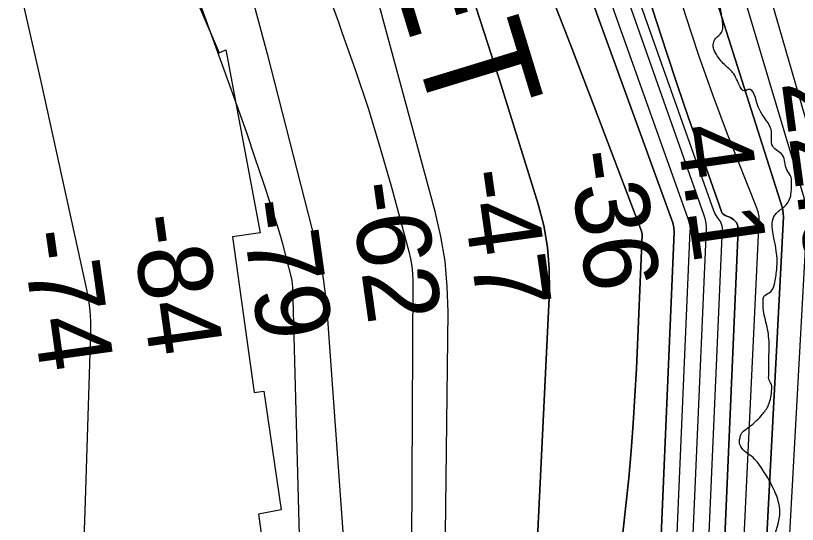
# Model space of a CAD drawing. Extents: x 3329297 to 3367176, y 649250 to 674653.
# Drawn here: x 3342123 to 3342831, y 664290 to 664750 of the extents above; entities that cross this region are included whole.
import ezdxf

# ---------------------------------------------------------------- set-up
doc = ezdxf.new("R2010")
doc.units = 0
for name, color, linetype in [('V-RIVR-EDGE', 7, 'Continuous'), ('V-RIVR-RANG', 7, 'Continuous'), ('V-RRAP-RVMT', 7, 'Continuous'), ('V-RRAP-RVMT-IDEN', 7, 'Continuous'), ('V-TOPO-DPTH', 7, 'Continuous'), ('V-TOPO-MAJR', 7, 'Continuous'), ('V-TOPO-MINR', 7, 'Continuous'), ('V-TOPO-WATR', 7, 'Continuous')]:
    doc.layers.add(name, color=color, linetype=linetype)

msp = doc.modelspace()

# ---------------------------------------------------------------- linework, layer by layer
at = {"layer": 'V-RIVR-EDGE'}
msp.add_spline([(3342816.41, 664076.7), (3342812.76, 664100.73), (3342811.24, 664114.69), (3342810.49, 664125.17), (3342811.67, 664129.43), (3342815.94, 664131.36), (3342822.14, 664130.96), (3342827.58, 664133.66), (3342827.98, 664138.7), (3342825.71, 664163.52), (3342823.01, 664169.35), (3342818.01, 664185.26), (3342816.5, 664200), (3342816.91, 664208.92), (3342818.1, 664220.94), (3342817.34, 664227.14), (3342814.66, 664243.44), (3342809.27, 664257.41), (3342808.51, 664264.01), (3342808.92, 664272.54), (3342814.79, 664296.18), (3342814.82, 664305.49), (3342810.59, 664319.46), (3342799.78, 664338.87), (3342790.88, 664350.14), (3342779.66, 664360.25), (3342778.51, 664365.3), (3342779.3, 664369.17), (3342779.69, 664370.72), (3342785.91, 664376.91), (3342798.35, 664388.13), (3342804.18, 664396.26), (3342807.71, 664410.21), (3342807.34, 664416.8), (3342805.02, 664421.46), (3342805.03, 664424.18), (3342805.05, 664435.04), (3342805.48, 664451.32), (3342803.59, 664468.39), (3342800.14, 664485.46), (3342800.15, 664492.05), (3342800.55, 664495.93), (3342805.6, 664499.41), (3342810.27, 664507.15), (3342811.45, 664513.74), (3342812.65, 664526.54), (3342808.84, 664554.08), (3342808.48, 664564.55), (3342811.98, 664571.52), (3342819.76, 664577.71), (3342825.21, 664588.56), (3342825.62, 664596.7), (3342825.25, 664604.07), (3342821.39, 664610.67), (3342817.54, 664623.86), (3342808.64, 664632.03), (3342807.5, 664639.01), (3342807.51, 664645.61), (3342805.59, 664651.04), (3342795.55, 664667.74), (3342786.28, 664683.28), (3342782.79, 664682.12), (3342779.3, 664685.62), (3342772.36, 664698.82), (3342765.01, 664705.82), (3342757.66, 664715.15), (3342754.96, 664720.97), (3342754.97, 664725.24), (3342756.92, 664729.5), (3342762.36, 664734.91), (3342763.16, 664745.77), (3342759.34, 664768.66), (3342756.66, 664780.69), (3342750.49, 664796.21), (3342738.91, 664818.35), (3342728.88, 664839.31), (3342718.83, 664850.59), (3342704.53, 664870.4), (3342673.21, 664906.93), (3342667.03, 664917.03), (3342662.4, 664928.67), (3342645.77, 664948.1), (3342638.82, 664957.43), (3342632.64, 664969.85), (3342630.72, 664978), (3342626.86, 664984.99), (3342614.87, 664996.66), (3342611.39, 664999.38), (3342609.84, 665001.32), (3342609.85, 665006.36), (3342606.76, 665010.25), (3342597.86, 665020.35), (3342593.22, 665025.41), (3342592.47, 665033.17), (3342590.94, 665044.42), (3342589.42, 665054.5), (3342588.28, 665065.36), (3342585.98, 665077), (3342585.23, 665086.7), (3342585.25, 665096.4), (3342584.88, 665101.05), (3342582.95, 665104.16), (3342580.25, 665109.59), (3342577.16, 665116.97), (3342577.18, 665122.79), (3342577.2, 665131.71), (3342577.22, 665142.56), (3342577.25, 665154.2), (3342576.12, 665167.77), (3342572.7, 665192.99), (3342566.93, 665215.11), (3342563.48, 665229.47), (3342558.85, 665239.95), (3342557.31, 665244.22), (3342555.4, 665255.47), (3342553.11, 665268.66), (3342549.27, 665284.57), (3342541.57, 665307.08), (3342537.34, 665321.83), (3342531.95, 665340.07), (3342533.51, 665343.55), (3342533.53, 665349.76), (3342526.98, 665368.39), (3342525.46, 665379.64), (3342523.54, 665388.18), (3342518.15, 665403.7), (3342515.47, 665416.12), (3342514.34, 665430.86), (3342508.57, 665450.65), (3342503.19, 665470.83), (3342492.38, 665490.63), (3342491.63, 665499.17), (3342490.87, 665508.48), (3342486.28, 665532.92), (3342483.6, 665545.33), (3342477.81, 665557.76), (3342475.93, 665580.26), (3342474.8, 665594.22), (3342470.17, 665605.48), (3342467.87, 665614.4), (3342467.13, 665629.53), (3342466.39, 665643.49), (3342466.82, 665662.1), (3342467.25, 665679.55), (3342463.41, 665695.46), (3342454.93, 665713.71), (3342445.67, 665732.35), (3342448.39, 665735.45), (3342449.55, 665735.05), (3342454.58, 665728.84), (3342456.13, 665730.38), (3342456.13, 665730.77), (3342455.37, 665734.65), (3342442.22, 665750.97), (3342428.7, 665771.56), (3342413.65, 665800.68), (3342398.6, 665832.52), (3342380.47, 665869.41), (3342358.86, 665914.06), (3342350, 665938.51), (3342337.27, 665963.36), (3342312.2, 666021.59), (3342297.17, 666058.47), (3342281.74, 666092.64), (3342274.81, 666112.43), (3342267.5, 666136.11), (3342262.92, 666165.98), (3342261.43, 666190.8), (3342261.45, 666198.56), (3342257.57, 666197.79), (3342255.25, 666199.74), (3342252.93, 666205.17), (3342252.57, 666212.54), (3342252.58, 666219.13), (3342250.29, 666232.71), (3342241.82, 666258.33), (3342236.07, 666285.87), (3342231.81, 666288.99), (3342227.55, 666291.71), (3342219.05, 666302.59), (3342218.67, 666306.86), (3342219.07, 666312.29), (3342210.16, 666314.25), (3342205.13, 666318.91), (3342203.98, 666324.35), (3342203.99, 666330.16), (3342202.08, 666339.09), (3342191.65, 666356.56), (3342180.04, 666369), (3342175.41, 666377.55), (3342164.99, 666396.96), (3342154.58, 666421.81), (3342139.95, 666463.34), (3342130.7, 666487.79), (3342122.99, 666506.43), (3342111.8, 666527.4), (3342098.68, 666554.19), (3342094.83, 666565.83), (3342092.54, 666581.74), (3342088.69, 666594.54), (3342085.25, 666612.78), (3342082.17, 666622.09), (3342072.89, 666631.81), (3342063.22, 666645.41), (3342057.44, 666657.83), (3342049.73, 666678.02), (3342048.22, 666693.14), (3342050.17, 666696.63), (3342050.96, 666704.38), (3342046.71, 666709.05), (3342039.36, 666716.82), (3342032.41, 666729.25), (3342015.81, 666761.09), (3342003.06, 666780.9), (3341996.09, 666786.35), (3341994.95, 666792.55), (3341992.63, 666796.44), (3341982.97, 666811.97), (3341967.13, 666835.28), (3341953.59, 666848.89), (3341946.63, 666857.44), (3341940.45, 666867.92), (3341935.81, 666874.14), (3341919.16, 666884.26), (3341915.69, 666890.09), (3341911.45, 666900.18), (3341899.85, 666913.78), (3341894.82, 666921.16), (3341889.03, 666931.65), (3341869.32, 666956.91), (3341855.01, 666974.78), (3341848.82, 666978.67), (3341839.53, 666986.84), (3341829.09, 667000.44), (3341821.76, 667015.19), (3341819.07, 667024.89), (3341817.15, 667031.1), (3341806.31, 667038.89), (3341788.13, 667056.77), (3341778.46, 667069.98), (3341769.56, 667076.21), (3341762.98, 667079.71), (3341756.02, 667089.04), (3341748.29, 667099.53), (3341738.62, 667112.35), (3341730.89, 667120.12), (3341719.29, 667133.73), (3341714.66, 667143.05), (3341706.55, 667156.64), (3341694.95, 667171.79), (3341682.22, 667198.97), (3341673.73, 667217.22), (3341665.66, 667244.77), (3341658.35, 667270.77), (3341654.5, 667280.86), (3341646.79, 667297.56), (3341633.67, 667325.51), (3341621.31, 667347.26), (3341603.92, 667370.57), (3341601.61, 667379.11), (3341595.05, 667392.31), (3341586.57, 667412.5), (3341578.1, 667435.79), (3341568.43, 667448.22), (3341554.13, 667467.65), (3341537.52, 667492.51), (3341516.66, 667523.97), (3341476.08, 667581.85), (3341429.71, 667650.22), (3341398.03, 667697.22), (3341370.98, 667737.23), (3341354.76, 667763.64), (3341343.55, 667778.41), (3341338.9, 667782.3), (3341332.33, 667790.07), (3341325.39, 667805.99), (3341317.65, 667814.15), (3341305.28, 667827.37), (3341300.64, 667833.19), (3341282.89, 667869.69), (3341259.72, 667911.24), (3341224.58, 667969.5), (3341190.57, 668018.45), (3341159.67, 668067), (3341126.02, 668105.48), (3341085.81, 668151.72), (3341034.77, 668213.12), (3340998.8, 668250.83), (3340967.07, 668282.32), (3340929.92, 668312.66), (3340887.35, 668349.99), (3340852.52, 668378), (3340818.08, 668406.01), (3340783.64, 668439.06), (3340747.67, 668475.99), (3340722.92, 668504.36), (3340704.36, 668525.73), (3340693.92, 668537.01), (3340680.75, 668543.24), (3340672.61, 668546.75), (3340664.48, 668552.59), (3340650.93, 668563.48), (3340645.91, 668568.92), (3340640.88, 668576.69), (3340634.7, 668584.08), (3340619.62, 668601.57), (3340609.54, 668604.69), (3340603.74, 668608.97), (3340599.1, 668614.41), (3340595.62, 668621.01), (3340589.43, 668627.24), (3340567.76, 668645.9), (3340549.95, 668659.13), (3340496.93, 668702.7), (3340430.76, 668760.64), (3340383.93, 668798.76), (3340346.77, 668824.45), (3340316.96, 668845.08), (3340289.86, 668863.37), (3340255.41, 668891.77), (3340209.37, 668936.09), (3340181.13, 668962.92), (3340159.06, 668977.32), (3340134.29, 668996.39), (3340120.75, 669009.22), (3340113.4, 669017.77), (3340109.92, 669023.59), (3340107.6, 669025.92), (3340099.85, 669026.72), (3340094.42, 669027.9), (3340089.39, 669030.24), (3340085.14, 669036.45), (3340084.76, 669043.04), (3340082.06, 669046.15), (3340066.19, 669058.99), (3340051.1, 669071.44), (3340041.8, 669077.66), (3339987.61, 669116.19), (3339929.52, 669149.3), (3339882.28, 669177.34), (3339823.8, 669212), (3339768.82, 669245.87), (3339704.94, 669289.46), (3339659.64, 669320.6), (3339613.98, 669359.49), (3339576.03, 669382.85), (3339562.87, 669392.97), (3339559.39, 669394.53), (3339555.89, 669394.15), (3339553.17, 669389.89), (3339550.84, 669388.73), (3339546.19, 669392.24), (3339540.39, 669395.35), (3339537.28, 669393.03), (3339533.01, 669392.66), (3339518.67, 669398.12), (3339507.83, 669404.74), (3339498.93, 669411.35), (3339490.01, 669411.38), (3339486.53, 669416.04), (3339483.43, 669417.6), (3339473.36, 669420.73), (3339460.58, 669427.74), (3339447.8, 669435.52), (3339435.41, 669443.31), (3339423.8, 669453.42), (3339413.36, 669464.7), (3339407.94, 669471.3), (3339393.62, 669479.48), (3339378.13, 669489.21), (3339357.61, 669502.45), (3339355.67, 669504.78), (3339358.39, 669506.33), (3339359.56, 669509.43), (3339359.18, 669510.98), (3339356.48, 669515.25), (3339347.17, 669516.82), (3339341.34, 669512.57), (3339338.24, 669513.36), (3339320.82, 669525.81), (3339311.15, 669534.75), (3339296.06, 669548.75), (3339293.35, 669550.31), (3339286.37, 669549.16), (3339280.93, 669546.46), (3339277.05, 669546.47), (3339268.14, 669549.98), (3339250.71, 669559.72), (3339229.04, 669575.67), (3339210.84, 669586.97), (3339202.33, 669595.13), (3339200.4, 669599.4), (3339200.02, 669604.83), (3339198.1, 669611.04), (3339183.01, 669622.71), (3339166.35, 669632.45)], degree=3, dxfattribs=at)
at = {"layer": 'V-RRAP-RVMT'}
for p, q in [((3342290.19, 664757.35), (3342307.62, 664716.49)), ((3342307.62, 664716.49), (3342313.85, 664719.1)), ((3342313.85, 664719.1), (3342344.64, 664553.67)), ((3342344.64, 664553.67), (3342319.79, 664549.9)), ((3342319.79, 664549.9), (3342339.2, 664409.04)), ((3342339.2, 664409.04), (3342348.14, 664410.37)), ((3342348.14, 664410.37), (3342363.8, 664302.78)), ((3342363.8, 664302.78), (3342343.39, 664298.89)), ((3342343.39, 664298.89), (3342361.53, 664168.96))]:
    msp.add_line(p, q, dxfattribs=at)
at = {"layer": 'V-TOPO-DPTH'}
for points in [[(3342213.91, 666344.24), (3342248.03, 666262.65), (3342280.72, 666180.47), (3342312.47, 666097.91), (3342483.02, 665642.52), (3342485.21, 665636.51), (3342487.34, 665630.48), (3342489.35, 665624.41), (3342491.3, 665618.32), (3342634.58, 665157.16), (3342664.89, 665059.88), (3342695.3, 664962.62), (3342725.85, 664865.41), (3342756.5, 664768.24), (3342817.37, 664575.8), (3342817.87, 664573.91), (3342818.26, 664571.02), (3342818.28, 664568.1), (3342772.99, 663696.25)], [(3342162.24, 666335.77), (3342410.61, 665656.31), (3342418.95, 665633.05), (3342427.09, 665609.73), (3342434.94, 665586.3), (3342442.6, 665562.81), (3342703.31, 664745.72), (3342712.82, 664716.35), (3342722.51, 664687.04), (3342732.45, 664657.82), (3342742.57, 664628.66), (3342762.18, 664572.94), (3342762.76, 664571.81), (3342763.49, 664570.82), (3342765.55, 664569.42), (3342770.48, 664567.43), (3342773.46, 664565.47), (3342775.75, 664563.07), (3342776.99, 664559.99), (3342777.54, 664556.46), (3342752.36, 663979.79), (3342746.15, 663858.52), (3342738.73, 663737.33)], [(3342738.73, 663737.33), (3342746.15, 663858.52), (3342752.36, 663979.79), (3342777.54, 664556.46), (3342776.99, 664559.99), (3342775.75, 664563.07), (3342773.46, 664565.47), (3342770.48, 664567.43), (3342765.55, 664569.42), (3342763.49, 664570.82), (3342762.76, 664571.81), (3342762.18, 664572.94), (3342742.57, 664628.66), (3342732.45, 664657.82), (3342722.51, 664687.04), (3342712.82, 664716.35), (3342703.31, 664745.72), (3342442.6, 665562.81), (3342434.94, 665586.3), (3342427.09, 665609.73), (3342418.95, 665633.05), (3342410.61, 665656.31), (3342162.24, 666335.77)], [(3342705.43, 663775.19), (3342713.14, 663863.53), (3342719.95, 663951.92), (3342725.4, 664040.42), (3342729.94, 664128.97), (3342748.63, 664557.09), (3342748.64, 664558.74), (3342748.39, 664562.04), (3342747.77, 664565.3), (3342746.89, 664568.51), (3342746.37, 664570.09), (3342482.89, 665316.86)], [(3342705.43, 663775.19), (3342713.14, 663863.53), (3342719.95, 663951.92), (3342725.4, 664040.42), (3342729.94, 664128.97), (3342748.63, 664557.09), (3342748.64, 664558.74), (3342748.39, 664562.04), (3342747.77, 664565.3), (3342746.89, 664568.51), (3342746.37, 664570.09), (3342482.89, 665316.86)], [(3342533.63, 665071.06), (3342718.12, 664562.58), (3342719.25, 664558.48), (3342719.57, 664554.25), (3342707.58, 664279.66), (3342704.68, 664223.08), (3342701.19, 664166.55), (3342696.83, 664110.07), (3342691.89, 664053.64), (3342686.26, 663997.26), (3342680.31, 663940.92), (3342673.85, 663884.64), (3342667.06, 663828.39)], [(3342667.06, 663828.39), (3342673.85, 663884.64), (3342680.31, 663940.92), (3342686.26, 663997.26), (3342691.89, 664053.64), (3342696.83, 664110.07), (3342701.19, 664166.55), (3342704.68, 664223.08), (3342707.58, 664279.66), (3342719.57, 664554.25), (3342719.25, 664558.48), (3342718.12, 664562.58), (3342533.63, 665071.06)], [(3342603.34, 664781.48), (3342625.3, 664724.75), (3342647.05, 664667.95), (3342689.86, 664555.07), (3342690.02, 664554.63), (3342690.45, 664552.81), (3342690.52, 664551.89), (3342690.51, 664551.42), (3342685.25, 664430.81), (3342683.97, 664405.97), (3342682.44, 664381.15), (3342680.53, 664356.35), (3342678.36, 664331.58), (3342675.85, 664306.83), (3342673.15, 664282.1), (3342670.17, 664257.41), (3342666.99, 664232.74), (3342659.05, 664173.8), (3342651.89, 664119.66), (3342644.89, 664065.5), (3342638.14, 664011.31), (3342631.55, 663957.1), (3342616.8, 663833.33)], [(3342603.34, 664781.48), (3342625.3, 664724.75), (3342647.05, 664667.95), (3342689.86, 664555.07), (3342690.02, 664554.63), (3342690.45, 664552.81), (3342690.52, 664551.89), (3342690.51, 664551.42), (3342685.25, 664430.81), (3342683.97, 664405.97), (3342682.44, 664381.15), (3342680.53, 664356.35), (3342678.36, 664331.58), (3342675.85, 664306.83), (3342673.15, 664282.1), (3342670.17, 664257.41), (3342666.99, 664232.74), (3342659.05, 664173.8), (3342651.89, 664119.66), (3342644.89, 664065.5), (3342638.14, 664011.31), (3342631.55, 663957.1), (3342616.8, 663833.33)], [(3342569.11, 663835.86), (3342578.82, 663976.8), (3342587.22, 664117.83), (3342594.73, 664258.91), (3342606.5, 664501.06), (3342606.41, 664520.97), (3342604.95, 664540.71), (3342601.42, 664560.18), (3342596.51, 664579.48), (3342561.1, 664693.1), (3342536.78, 664768.86)], [(3342536.78, 664768.86), (3342561.1, 664693.1), (3342596.51, 664579.48), (3342601.42, 664560.18), (3342604.95, 664540.71), (3342606.41, 664520.97), (3342606.5, 664501.06), (3342594.73, 664258.91), (3342587.22, 664117.83), (3342578.82, 663976.8), (3342569.11, 663835.86)]]:
    msp.add_lwpolyline(points, dxfattribs=at)
at = {"layer": 'V-TOPO-MAJR'}
msp.add_lwpolyline([(3342499.49, 663200.43), (3342514.84, 664482.04), (3342514.16, 664505.02), (3342512.21, 664527.83), (3342508.37, 664550.41), (3342503.28, 664572.82), (3342448.74, 664773.43), (3342413.78, 664895.5), (3342376.64, 665016.87), (3342336.24, 665137.2), (3342293.66, 665256.83), (3342193.8, 665525.86), (3342193.46, 665526.77), (3342193.28, 665527.23), (3342193.11, 665527.68), (3342191.1, 665532.94), (3342189.91, 665536.02), (3342188.71, 665539.1), (3342187.49, 665542.17), (3342186.27, 665545.24), (3341820.92, 666452.1)], dxfattribs=at)
at = {"layer": 'V-TOPO-MINR'}
for points in [[(3342781.67, 663507.75), (3342840.16, 664572.02), (3342839.86, 664575.67), (3342839.73, 664576.18), (3342714.04, 664997.71), (3342681.72, 665105.22), (3342649.08, 665212.63), (3342615.94, 665319.89), (3342582.49, 665427.05), (3342527.81, 665600.81), (3342521.29, 665620.96), (3342514.57, 665641.05), (3342507.55, 665661.02), (3342500.32, 665680.93), (3342438.57, 665846.96), (3342399.38, 665949.45), (3342358.95, 666051.43), (3342316.65, 666152.66), (3342273.11, 666253.38), (3342138.95, 666556.06)], [(3342790.17, 663312.79), (3342862.06, 664575.94), (3342862.06, 664576.02), (3342862.06, 664576.17), (3342862.02, 664576.48), (3342862, 664576.56), (3342632.01, 665369.62), (3342618.1, 665417), (3342603.97, 665464.31), (3342589.53, 665511.54), (3342574.88, 665558.69), (3342567.67, 665581.62), (3342556.18, 665617.17), (3342544.32, 665652.59), (3342531.89, 665687.81), (3342519.08, 665722.9), (3342511.04, 665744.42), (3342493.52, 665790), (3342475.45, 665835.37), (3342456.57, 665880.4), (3342437.14, 665925.21), (3342160.51, 666547.74)], [(3342772.99, 663696.25), (3342818.28, 664568.1), (3342818.26, 664571.02), (3342817.87, 664573.91), (3342817.37, 664575.8), (3342756.5, 664768.24), (3342725.85, 664865.41), (3342695.3, 664962.62), (3342664.89, 665059.88), (3342634.58, 665157.16), (3342491.3, 665618.32), (3342489.35, 665624.41), (3342487.34, 665630.48), (3342485.21, 665636.51), (3342483.02, 665642.52), (3342312.47, 666097.91), (3342280.72, 666180.47), (3342248.03, 666262.65), (3342213.91, 666344.24)], [(3342683.73, 663770.19), (3342691.42, 663842.36), (3342698.66, 663914.59), (3342704.98, 663986.89), (3342710.56, 664059.25), (3342715.03, 664131.68), (3342718.75, 664204.17), (3342734.1, 664555.67), (3342734.11, 664557.03), (3342733.91, 664559.74), (3342733.4, 664562.41), (3342732.25, 664566.34), (3342446.55, 665368.48)], [(3342705.43, 663775.19), (3342713.14, 663863.53), (3342719.95, 663951.92), (3342725.4, 664040.42), (3342729.94, 664128.97), (3342748.63, 664557.09), (3342748.64, 664558.74), (3342748.39, 664562.04), (3342747.77, 664565.3), (3342746.89, 664568.51), (3342746.37, 664570.09), (3342482.89, 665316.86)], [(3342667.06, 663828.39), (3342673.85, 663884.64), (3342680.31, 663940.92), (3342686.26, 663997.26), (3342691.89, 664053.64), (3342696.83, 664110.07), (3342701.19, 664166.55), (3342704.68, 664223.08), (3342707.58, 664279.66), (3342719.57, 664554.25), (3342719.25, 664558.48), (3342718.12, 664562.58), (3342533.63, 665071.06)], [(3342405.32, 663343.65), (3342374.3, 664504.93), (3342374.19, 664506.74), (3342373.69, 664510.33), (3342373.3, 664512.1), (3342368.27, 664531.9), (3342365.19, 664543.53), (3342361.94, 664555.11), (3342358.44, 664566.62), (3342354.79, 664578.08), (3342347.76, 664599.32), (3342340.38, 664621.33), (3342332.88, 664643.3), (3342325.19, 664665.2), (3342317.38, 664687.06), (3342230.83, 664926.14)], [(3342323.91, 664817.04), (3342350.98, 664715.74), (3342395, 664544.46), (3342398.65, 664528.45), (3342401.72, 664512.34), (3342403.92, 664496.1), (3342405.53, 664479.75), (3342422.49, 664241.07), (3342430.12, 664105.27), (3342435.07, 663969.41), (3342436, 663833.47)], [(3342122.79, 664793.95), (3342146.29, 664690.53), (3342187.61, 664502.38), (3342189.34, 664492.82), (3342190.59, 664483.22), (3342191.13, 664473.56), (3342191.19, 664463.84), (3342186.17, 664301.7), (3342182.7, 664210.91), (3342178.35, 664120.18), (3342172.69, 664029.52), (3342166.16, 663938.9), (3342106.54, 663188.18)], [(3342400.83, 664784.68), (3342415.23, 664745.1), (3342418.84, 664735.25), (3342431.09, 664700.48), (3342442.72, 664665.52), (3342453.45, 664630.27), (3342463.58, 664594.83), (3342479.41, 664536.6), (3342480.9, 664530.09), (3342482.03, 664523.54), (3342482.63, 664516.91), (3342482.87, 664510.24), (3342481.86, 664270.8), (3342480.39, 664144.4), (3342477.67, 664018.03), (3342473.09, 663891.72), (3342467.26, 663765.45)], [(3342721.3, 663740.03), (3342729.33, 663844.63), (3342735.77, 663949.34), (3342741.14, 664054.12), (3342763.13, 664557.83), (3342762.95, 664560.02), (3342761.46, 664563.98), (3342758.67, 664567.48), (3342756.3, 664571.3), (3342755.41, 664573.39), (3342681.43, 664782.34)], [(3342756.89, 663752.76), (3342763.85, 663878.89), (3342796.44, 664564.17), (3342796.47, 664565.6), (3342796.29, 664568.44), (3342795.46, 664572.64), (3342795.03, 664574), (3342794.55, 664575.34), (3342767.79, 664643.05), (3342754.39, 664678.4), (3342741.65, 664713.99), (3342729.91, 664749.91), (3342718.84, 664786.06)], [(3342616.8, 663833.33), (3342631.55, 663957.1), (3342638.14, 664011.31), (3342644.89, 664065.5), (3342651.89, 664119.66), (3342659.05, 664173.8), (3342666.99, 664232.74), (3342670.17, 664257.41), (3342673.15, 664282.1), (3342675.85, 664306.83), (3342678.36, 664331.58), (3342680.53, 664356.35), (3342682.44, 664381.15), (3342683.97, 664405.97), (3342685.25, 664430.81), (3342690.51, 664551.42), (3342690.52, 664551.89), (3342690.45, 664552.81), (3342690.02, 664554.63), (3342689.86, 664555.07), (3342647.05, 664667.95), (3342625.3, 664724.75), (3342603.34, 664781.48)], [(3342569.11, 663835.86), (3342578.82, 663976.8), (3342587.22, 664117.83), (3342594.73, 664258.91), (3342606.5, 664501.06), (3342606.41, 664520.97), (3342604.95, 664540.71), (3342601.42, 664560.18), (3342596.51, 664579.48), (3342561.1, 664693.1), (3342536.78, 664768.86)]]:
    msp.add_lwpolyline(points, dxfattribs=at)
at = {"layer": 'V-TOPO-WATR'}
msp.add_lwpolyline([(3342738.73, 663737.33), (3342746.15, 663858.52), (3342752.36, 663979.79), (3342777.54, 664556.46), (3342776.99, 664559.99), (3342775.75, 664563.07), (3342773.46, 664565.47), (3342770.48, 664567.43), (3342765.55, 664569.42), (3342763.49, 664570.82), (3342762.76, 664571.81), (3342762.18, 664572.94), (3342742.57, 664628.66), (3342732.45, 664657.82), (3342722.51, 664687.04), (3342712.82, 664716.35), (3342703.31, 664745.72), (3342442.6, 665562.81), (3342434.94, 665586.3), (3342427.09, 665609.73), (3342418.95, 665633.05), (3342410.61, 665656.31), (3342162.24, 666335.77)], dxfattribs=at)

# ---------------------------------------------------------------- texts
at = {"layer": 'V-RIVR-RANG'}
for s, rotation, p in [('22.9', 277.73833, (3342816.66, 664689.99)), ('4.1', 278.02081, (3342720.91, 664648.61)), ('-36', 278.02081, (3342623.14, 664625.76)), ('-47', 278.02081, (3342524.56, 664608.66)), ('-62', 278.02081, (3342425.18, 664597.3)), ('-79', 278.02081, (3342326.45, 664581.24)), ('-84', 278.02081, (3342227.32, 664568.05)), ('-74', 278.02081, (3342128.34, 664553.82))]:
    msp.add_text(s, height=67, rotation=rotation, dxfattribs=at).set_placement(p)
at = {"layer": 'V-RRAP-RVMT-IDEN'}
msp.add_text('REVET', height=100, rotation=287.00855, dxfattribs=at).set_placement((3342375.54, 665073.57))

doc.saveas('drawing.dxf')
